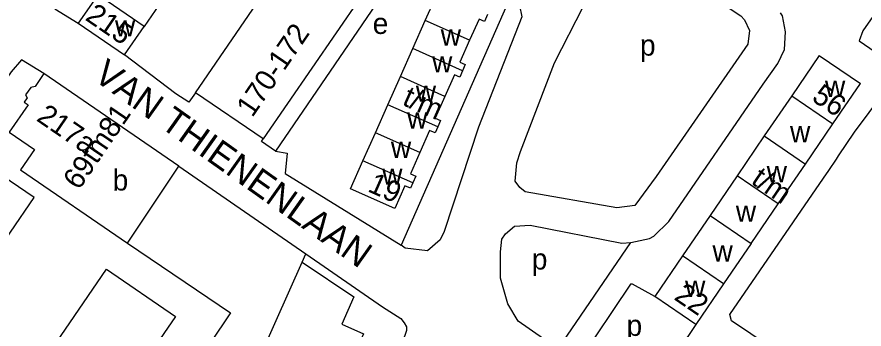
# Model space of a CAD drawing. Extents: x 159294 to 161936, y 384538 to 386517.
# Drawn here: x 160107.9 to 160269, y 385376.6 to 385435.9 of the extents above; entities that cross this region are included whole.
import ezdxf

# ---------------------------------------------------------------- set-up
doc = ezdxf.new("R2010")
doc.units = 0
for name, color, linetype in [('BLT_Basislijn', 7, 'Continuous'), ('BLT_Bebouwing', 7, 'Continuous'), ('BLT_Centroide', 7, 'Continuous'), ('BLT_Huisnummer', 7, 'Continuous'), ('BLT_Huisnummer_reeks', 7, 'Continuous'), ('BLT_Onderverdeling_panden', 7, 'Continuous'), ('BLT_Straatnaam', 7, 'Continuous')]:
    doc.layers.add(name, color=color, linetype=linetype)

msp = doc.modelspace()

# ---------------------------------------------------------------- linework, layer by layer
at = {"layer": 'BLT_Basislijn'}
for p, q in [((160202.46, 385441.36), (160180.93, 385392.51)), ((160262.3, 385406.7), (160263.77, 385408.87)), ((160263.77, 385408.87), (160264.18, 385409.49)), ((160138.66, 385407.53), (160162.8, 385390.88)), ((160261.32, 385405.27), (160262.3, 385406.7)), ((160210.79, 385372.8), (160224.65, 385393.03)), ((160162.09, 385389.27), (160162.8, 385390.88)), ((160162.8, 385390.88), (160177.4, 385380.8)), ((160237.02, 385377.44), (160226.72, 385362.24))]:
    msp.add_line(p, q, dxfattribs=at)
for points in [[(160148.58, 385477.12), (160144.27, 385480.27), (160134.3, 385466.36), (160115.03, 385437.49), (160119.5, 385434.72)], [(160229.49, 385405.57), (160225.41, 385400.07), (160222, 385399.59), (160204.56, 385402.68), (160203.51, 385403.47), (160202.65, 385404.68), (160202.97, 385408.18), (160203.67, 385410.35), (160210.13, 385427.22), (160221.17, 385448.8), (160222.96, 385449.64), (160225.33, 385449.52), (160245.56, 385436.12), (160246.27, 385435.37), (160247.21, 385433.33), (160246.89, 385430.78), (160229.49, 385405.57)], [(160279.59, 385448.77), (160268.8, 385433.3), (160268.09, 385431.41), (160280.47, 385422.91), (160292.49, 385398.16)], [(160202.46, 385441.36), (160203, 385440.33), (160203.93, 385435.95), (160195.7, 385414.98), (160189.15, 385395.09), (160188.4, 385393.51), (160185.94, 385391.47), (160181.74, 385391.95), (160180.93, 385392.51)], [(160224.65, 385393.03), (160228.18, 385393.81), (160229, 385394.25), (160231.88, 385397.05), (160249.85, 385423.12), (160252.6, 385427.1), (160253.9, 385429.73), (160254.1, 385433.11), (160253.53, 385436.12), (160253.14, 385436.72)], [(160112.98, 385425.16), (160108.7, 385427.78), (160106.78, 385425.49), (160077.49, 385382.87), (160077.49, 385381.69), (160077.82, 385379.83), (160080.58, 385377.75)], [(160141.8, 385421.52), (160140.55, 385419.72), (160138.1, 385421.32), (160128.3, 385428.69)], [(160264.18, 385409.49), (160267.23, 385414.04), (160272.82, 385421.51), (160276.72, 385418.75), (160286.25, 385398.26)], [(160157.04, 385410.4), (160159.28, 385410.02), (160158.88, 385406.18), (160180.93, 385392.51)], [(160255.02, 385370.57), (160243.82, 385378.1), (160243.5, 385379.35), (160261.32, 385405.27)], [(160210.79, 385372.8), (160203.19, 385378.09), (160201.25, 385381.35), (160199.83, 385386.22), (160199.86, 385391.27), (160200.1, 385393.64), (160200.8, 385394.66), (160202.55, 385396.15), (160205.51, 385396.33), (160222.97, 385392.92), (160224.65, 385393.03)], [(160128.88, 385392.89), (160148.46, 385379.62), (160124.9, 385344.45)], [(160229.21, 385382.78), (160224.99, 385385.11), (160224.56, 385385.07), (160214.63, 385370.28)], [(160177.4, 385380.8), (160180.87, 385378.54), (160181.55, 385377.75), (160181.96, 385376.99), (160181.96, 385376.26), (160181.2, 385374.07), (160160.28, 385326.08), (160159.28, 385324.12), (160158.16, 385323.52), (160155.46, 385323.48), (160153.54, 385324.85)]]:
    msp.add_lwpolyline(points, dxfattribs=at)
at = {"layer": 'BLT_Bebouwing'}
for p, q in [((160141.8, 385421.52), (160166.73, 385457.87)), ((160182.26, 385447.36), (160157.04, 385410.4)), ((160123.24, 385440.16), (160119.5, 385434.72)), ((160185.55, 385435.25), (160187.92, 385440.59)), ((160119.5, 385434.72), (160128.3, 385428.69)), ((160183.17, 385429.91), (160185.55, 385435.25)), ((160128.3, 385428.69), (160132.03, 385434.13)), ((160180.8, 385424.58), (160183.17, 385429.91)), ((160260.5, 385428.6), (160255.26, 385420.95)), ((160260.5, 385428.6), (160268.32, 385423.26)), ((160138.66, 385407.53), (160112.98, 385425.16)), ((160178.43, 385419.24), (160180.8, 385424.58)), ((160263.09, 385415.6), (160268.32, 385423.26)), ((160255.26, 385420.95), (160250.02, 385413.3)), ((160176.06, 385413.9), (160178.43, 385419.24)), ((160257.86, 385407.95), (160263.09, 385415.6)), ((160173.69, 385408.56), (160176.06, 385413.9)), ((160250.02, 385413.3), (160244.87, 385405.73)), ((160128.88, 385392.89), (160138.66, 385407.53)), ((160252.7, 385400.39), (160257.86, 385407.95)), ((160244.87, 385405.73), (160239.73, 385398.17)), ((160247.54, 385392.83), (160252.7, 385400.39)), ((160239.73, 385398.17), (160234.47, 385390.47)), ((160247.54, 385392.83), (160242.28, 385385.14)), ((160234.47, 385390.47), (160229.21, 385382.78)), ((160242.28, 385385.14), (160237.02, 385377.44)), ((160237.02, 385377.44), (160229.21, 385382.78))]:
    msp.add_line(p, q, dxfattribs=at)
for points in [[(160132.03, 385434.13), (160132.11, 385434.08), (160135.63, 385439.22), (160135.12, 385439.57)], [(160197.4, 385436.38), (160196.82, 385435.06), (160195.77, 385435.53), (160193.98, 385431.5)], [(160193.98, 385431.5), (160192.13, 385427.32), (160193.16, 385426.86), (160192.65, 385425.7)], [(160112.98, 385425.16), (160111.29, 385422.68), (160110.48, 385422.53), (160109.5, 385421.11), (160109.78, 385420.51), (160109.22, 385419.69), (160109.96, 385419.18), (160106.4, 385413.99), (160111.2, 385410.7), (160108.55, 385406.83), (160128.88, 385392.89)], [(160192.65, 385425.7), (160192.1, 385424.46), (160191.08, 385424.91), (160189.26, 385420.82)], [(160154.7, 385412.72), (160141.8, 385421.52)], [(160189.26, 385420.82), (160187.41, 385416.66), (160188.44, 385416.2), (160187.92, 385415.02)], [(160187.92, 385415.02), (160187.41, 385413.88), (160186.37, 385414.34), (160184.51, 385410.14)], [(160157.04, 385410.4), (160154.37, 385412.23), (160154.7, 385412.72)], [(160184.51, 385410.14), (160182.71, 385406.1), (160183.72, 385405.65), (160183.15, 385404.35)], [(160183.15, 385404.35), (160182.7, 385403.35), (160181.68, 385403.81), (160179.75, 385399.47), (160171.32, 385403.22), (160173.69, 385408.56)], [(160100.49, 385362.91), (160103.32, 385367.04), (160103.84, 385367.79), (160093.03, 385375.21), (160111.11, 385401.57), (160106.56, 385404.68), (160102.44, 385407.51), (160098.11, 385401.21), (160096.43, 385398.78), (160085.4, 385382.7), (160084.43, 385383.37), (160080.58, 385377.75)], [(160139.5, 385338.47), (160162.09, 385389.27)], [(160162.09, 385389.27), (160171.95, 385382.66), (160169.67, 385377.5), (160173.77, 385375.67), (160156.01, 385335.65)], [(160138.01, 385378.97), (160126.07, 385361.56), (160127.94, 385360.27), (160122.62, 385352.52), (160109.57, 385361.47), (160114.62, 385368.83), (160112.69, 385370.16), (160124.9, 385387.96), (160138.01, 385378.97)]]:
    msp.add_lwpolyline(points, dxfattribs=at)
at = {"layer": 'BLT_Onderverdeling_panden'}
for p, q in [((160179.7, 385449.1), (160154.7, 385412.72)), ((160132.03, 385434.13), (160123.24, 385440.16)), ((160193.98, 385431.5), (160185.55, 385435.25)), ((160192.65, 385425.7), (160183.17, 385429.91)), ((160189.26, 385420.82), (160180.8, 385424.58)), ((160255.26, 385420.95), (160263.09, 385415.6)), ((160187.92, 385415.02), (160178.43, 385419.24)), ((160184.51, 385410.14), (160176.06, 385413.9)), ((160250.02, 385413.3), (160257.86, 385407.95)), ((160183.15, 385404.35), (160173.69, 385408.56)), ((160252.7, 385400.39), (160244.87, 385405.73)), ((160239.73, 385398.17), (160247.54, 385392.83)), ((160242.28, 385385.14), (160234.47, 385390.47))]:
    msp.add_line(p, q, dxfattribs=at)

# ---------------------------------------------------------------- texts
at = {"layer": 'BLT_Centroide'}
for s, p in [('e', (160175.54, 385432.69)), ('w', (160126.5, 385432.23)), ('w', (160188.48, 385430.47)), ('p', (160226.39, 385428.57)), ('w', (160186.83, 385425.38)), ('w', (160261.59, 385420.73)), ('w', (160183.74, 385419.81)), ('w', (160182.09, 385414.69)), ('w', (160254.94, 385412.09)), ('w', (160179, 385409.12)), ('b', (160126.06, 385402.91)), ('w', (160177.34, 385404)), ('w', (160250.5, 385404.5)), ('w', (160244.63, 385396.97)), ('w', (160240.19, 385389.41)), ('p', (160205.81, 385387.88)), ('w', (160234.97, 385382.69)), ('p', (160223.84, 385375.26))]:
    msp.add_text(s, height=4, dxfattribs=at).set_placement(p)
at = {"layer": 'BLT_Huisnummer'}
msp.add_text('215', height=4, rotation=325.5574, dxfattribs=at).set_placement((160120.65, 385435.48))
at = {"layer": 'BLT_Huisnummer_reeks'}
for s, rotation, p in [('170-172', 55.6858, (160152.63, 385416.66)), ('56', 325.6745, (160258.87, 385420.14)), ('t/m', 336.0274, (160180.97, 385419.28)), ('217a', 325.562, (160111.37, 385416.32)), ('69tm81', 55.6858, (160119.64, 385402.84)), ('t/m', 325.6726, (160247.32, 385404.36)), ('19', 336.0507, (160174.39, 385402.83)), ('22', 325.6772, (160232.69, 385382.3))]:
    msp.add_text(s, height=4, rotation=rotation, dxfattribs=at).set_placement(p)
at = {"layer": 'BLT_Straatnaam'}
msp.add_text('VAN THIENENLAAN', height=5, rotation=324.619, dxfattribs=at).set_placement((160122.15, 385424.12))

doc.saveas('drawing.dxf')
